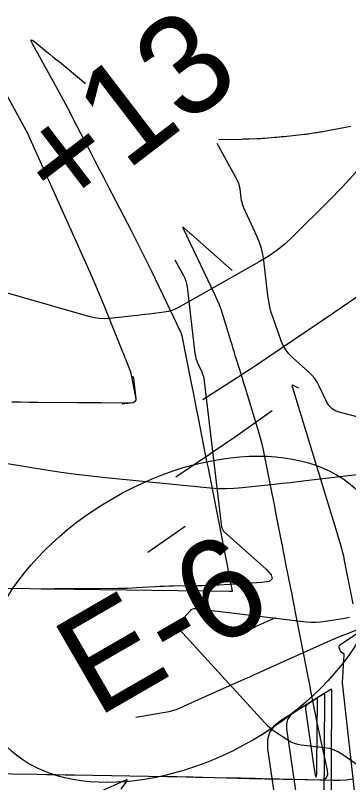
# Model space of a CAD drawing. Extents: x 1005228 to 1008882, y 1883389 to 1885754.
# Drawn here: x 1008057.01 to 1008077.87, y 1884530.66 to 1884578.71 of the extents above; entities that cross this region are included whole.
import ezdxf

# ---------------------------------------------------------------- set-up
doc = ezdxf.new("R2010")
doc.units = 0
for name, color, linetype in [('ATDIMS', 7, 'Continuous'), ('C-ANNO-NOTE', 7, 'Continuous'), ('R_Erosion', 7, 'Continuous'), ('S_BASELINE', 7, 'Continuous'), ('S_BRIDGE', 7, 'Continuous'), ('TSOBSTACLE', 7, 'Continuous')]:
    doc.layers.add(name, color=color, linetype=linetype)

msp = doc.modelspace()

# ---------------------------------------------------------------- linework, layer by layer
at = {"layer": 'ATDIMS'}
for points in [[(1008073.086, 1884553.939), (1008070.574, 1884552.176), (1008070.225, 1884551.932), (1008069.874, 1884551.689), (1008069.523, 1884551.448), (1008069.17, 1884551.209), (1008067.05, 1884549.779)], [(1008063.643, 1884530.239), (1008063.954, 1884530.685), (1008064.007, 1884530.776), (1008064.009, 1884530.824), (1008063.961, 1884530.831), (1008063.862, 1884530.795), (1008062.288, 1884530.078)]]:
    msp.add_lwpolyline(points, dxfattribs=at)
at = {"layer": 'C-ANNO-NOTE'}
for points in [[(1008078.722, 1884569.319), (1008077.714, 1884568.219), (1008077.461, 1884567.946), (1008077.204, 1884567.675), (1008076.944, 1884567.408), (1008076.681, 1884567.143), (1008074.378, 1884564.856), (1008073.893, 1884564.405), (1008073.381, 1884563.989), (1008072.842, 1884563.608), (1008072.277, 1884563.263), (1008067.228, 1884560.405), (1008067.015, 1884560.298), (1008066.796, 1884560.214), (1008066.569, 1884560.152), (1008066.334, 1884560.113), (1008065.382, 1884560.001), (1008065.144, 1884559.973), (1008064.906, 1884559.946), (1008064.668, 1884559.919), (1008064.429, 1884559.893), (1008062.915, 1884559.73), (1008062.585, 1884559.71), (1008062.257, 1884559.722), (1008061.933, 1884559.766), (1008061.61, 1884559.842), (1008046.977, 1884564.044)], [(1008077.93, 1884540.998), (1008077.629, 1884540.943), (1008076.42, 1884540.738), (1008076.118, 1884540.698), (1008075.815, 1884540.679), (1008075.512, 1884540.683), (1008075.208, 1884540.709), (1008068.293, 1884541.543), (1008068.186, 1884541.544), (1008068.089, 1884541.52), (1008068.002, 1884541.472), (1008067.924, 1884541.4), (1008067.583, 1884541.006), (1008067.535, 1884540.948), (1008067.488, 1884540.888), (1008067.444, 1884540.826), (1008067.402, 1884540.762), (1008067.24, 1884540.505), (1008067.211, 1884540.441), (1008067.205, 1884540.38), (1008067.222, 1884540.321), (1008067.262, 1884540.263), (1008072.605, 1884534.427), (1008072.764, 1884534.263), (1008072.933, 1884534.11), (1008073.111, 1884533.967), (1008073.298, 1884533.835), (1008074.064, 1884533.329), (1008074.26, 1884533.215), (1008074.465, 1884533.126), (1008074.68, 1884533.062), (1008074.903, 1884533.024), (1008076.347, 1884532.861), (1008076.657, 1884532.807), (1008076.952, 1884532.716), (1008077.234, 1884532.588), (1008077.502, 1884532.423), (1008087.661, 1884525.295)]]:
    msp.add_lwpolyline(points, dxfattribs=at)
at = {"layer": 'R_Erosion'}
msp.add_ellipse((1008067.488, 1884540.888), major_axis=(11.853, 6.865), ratio=0.638788, dxfattribs=at)
at = {"layer": 'S_BRIDGE'}
msp.add_lwpolyline([(1008055.231, 1884550.845), (1008058.949, 1884550.25), (1008059.88, 1884550.109), (1008060.812, 1884549.981), (1008061.746, 1884549.867), (1008062.682, 1884549.768), (1008069.204, 1884549.124), (1008069.704, 1884549.087), (1008070.204, 1884549.077), (1008070.704, 1884549.092), (1008071.204, 1884549.133), (1008073.203, 1884549.349), (1008073.703, 1884549.403), (1008074.202, 1884549.459), (1008074.702, 1884549.516), (1008075.201, 1884549.574), (1008079.295, 1884550.057)], dxfattribs=at)
at = {"layer": 'TSOBSTACLE'}
for points in [[(1008054.032, 1884578.139), (1008057.668, 1884571.525), (1008057.68, 1884571.501), (1008057.693, 1884571.478), (1008057.705, 1884571.454), (1008057.716, 1884571.43), (1008057.763, 1884571.334), (1008057.774, 1884571.31), (1008057.786, 1884571.286), (1008057.797, 1884571.262), (1008057.808, 1884571.238), (1008057.897, 1884571.038), (1008061.585, 1884562.819), (1008061.823, 1884562.281), (1008062.056, 1884561.741), (1008062.283, 1884561.199), (1008062.505, 1884560.654), (1008063.721, 1884557.631), (1008063.771, 1884557.506), (1008063.821, 1884557.381), (1008063.871, 1884557.256), (1008063.922, 1884557.131), (1008064.184, 1884556.479), (1008064.203, 1884556.43), (1008064.219, 1884556.38), (1008064.233, 1884556.329), (1008064.244, 1884556.278), (1008064.285, 1884556.07), (1008064.306, 1884555.966), (1008064.326, 1884555.863), (1008064.535, 1884554.8), (1008064.544, 1884554.63), (1008064.493, 1884554.509), (1008064.384, 1884554.437), (1008064.215, 1884554.415), (1008062.385, 1884554.433), (1008062.014, 1884554.436), (1008061.643, 1884554.44), (1008061.272, 1884554.443), (1008060.901, 1884554.447), (1008058.408, 1884554.468), (1008057.869, 1884554.472), (1008057.33, 1884554.476), (1008056.791, 1884554.478)], [(1008054.5, 1884542.843), (1008057.932, 1884542.81), (1008058.626, 1884542.803), (1008059.319, 1884542.795), (1008060.013, 1884542.786), (1008060.706, 1884542.777), (1008070.384, 1884542.64), (1008070.427, 1884542.64), (1008070.47, 1884542.639), (1008070.576, 1884542.637), (1008070.586, 1884542.638), (1008070.592, 1884542.642), (1008070.595, 1884542.649), (1008070.595, 1884542.659), (1008070.58, 1884542.732), (1008070.576, 1884542.756), (1008069.26, 1884549.485), (1008069.176, 1884549.916), (1008069.091, 1884550.346), (1008069.006, 1884550.776), (1008068.921, 1884551.206), (1008068.488, 1884553.387), (1008068.448, 1884553.587), (1008068.409, 1884553.787), (1008068.369, 1884553.987), (1008068.33, 1884554.187), (1008068.173, 1884554.987), (1008068.133, 1884555.187), (1008068.094, 1884555.387), (1008068.054, 1884555.587), (1008068.015, 1884555.787), (1008067.45, 1884558.638), (1008067.448, 1884558.648), (1008067.445, 1884558.659), (1008067.443, 1884558.669), (1008067.44, 1884558.679), (1008067.418, 1884558.749), (1008067.412, 1884558.768), (1008067.409, 1884558.777), (1008067.405, 1884558.786), (1008067.366, 1884558.868), (1008065.55, 1884562.657), (1008065.244, 1884563.29), (1008064.932, 1884563.92), (1008064.616, 1884564.549), (1008064.294, 1884565.174), (1008062.803, 1884568.049), (1008062.539, 1884568.556), (1008062.276, 1884569.063), (1008062.013, 1884569.57), (1008061.75, 1884570.078), (1008060.698, 1884572.107), (1008060.434, 1884572.613), (1008060.166, 1884573.118), (1008059.895, 1884573.621), (1008059.621, 1884574.123), (1008058.08, 1884576.926), (1008058.001, 1884577.094), (1008057.998, 1884577.17), (1008058.072, 1884577.154), (1008058.224, 1884577.046), (1008058.983, 1884576.426), (1008059.173, 1884576.272), (1008059.363, 1884576.117), (1008059.553, 1884575.962), (1008059.743, 1884575.807), (1008061.406, 1884574.447)], [(1008078.007, 1884571.751), (1008076.126, 1884571.399), (1008076.041, 1884571.384), (1008075.957, 1884571.369), (1008075.872, 1884571.355), (1008075.788, 1884571.341), (1008075.449, 1884571.289), (1008075.364, 1884571.276), (1008075.279, 1884571.265), (1008075.194, 1884571.254), (1008075.109, 1884571.244), (1008073.826, 1884571.106), (1008073.68, 1884571.09), (1008073.534, 1884571.076), (1008073.388, 1884571.063), (1008073.241, 1884571.05), (1008072.601, 1884570.998), (1008072.482, 1884570.989), (1008072.363, 1884570.981), (1008072.244, 1884570.975), (1008072.125, 1884570.97), (1008071.648, 1884570.953), (1008071.529, 1884570.949), (1008071.41, 1884570.945), (1008071.29, 1884570.943), (1008071.171, 1884570.941), (1008069.742, 1884570.919)], [(1008078.727, 1884553.491), (1008077.274, 1884553.858), (1008077.025, 1884553.949), (1008076.813, 1884554.085), (1008076.639, 1884554.266), (1008076.502, 1884554.493), (1008076.031, 1884555.493), (1008075.902, 1884555.734), (1008075.751, 1884555.96), (1008075.578, 1884556.168), (1008075.383, 1884556.36), (1008074.35, 1884557.282), (1008074.126, 1884557.508), (1008073.935, 1884557.756), (1008073.777, 1884558.027), (1008073.652, 1884558.32), (1008073.143, 1884559.758), (1008073.031, 1884560.101), (1008072.94, 1884560.449), (1008072.868, 1884560.801), (1008072.816, 1884561.158), (1008072.56, 1884563.347), (1008072.5, 1884563.731), (1008072.411, 1884564.107), (1008072.293, 1884564.476), (1008072.146, 1884564.836), (1008071.3, 1884566.705), (1008071.244, 1884566.841), (1008071.2, 1884566.979), (1008071.166, 1884567.121), (1008071.144, 1884567.265), (1008071.075, 1884567.85), (1008071.051, 1884567.994), (1008071.013, 1884568.134), (1008070.963, 1884568.269), (1008070.899, 1884568.4), (1008069.653, 1884570.675)], [(1008055.129, 1884531.232), (1008058.394, 1884531.177), (1008058.969, 1884531.167), (1008059.544, 1884531.158), (1008060.119, 1884531.148), (1008060.695, 1884531.139), (1008066.52, 1884531.043), (1008066.668, 1884531.04), (1008066.815, 1884531.038), (1008066.963, 1884531.035), (1008067.111, 1884531.032), (1008067.702, 1884531.021), (1008067.849, 1884531.018), (1008067.997, 1884531.015), (1008068.145, 1884531.012), (1008068.293, 1884531.009), (1008070.674, 1884530.959), (1008071.12, 1884530.949), (1008071.567, 1884530.939), (1008072.013, 1884530.928), (1008072.459, 1884530.917), (1008076.043, 1884530.823), (1008076.319, 1884530.856), (1008076.496, 1884530.97), (1008076.575, 1884531.166), (1008076.554, 1884531.443), (1008076.178, 1884533.157), (1008076.156, 1884533.254), (1008076.135, 1884533.352), (1008076.113, 1884533.449), (1008076.092, 1884533.546), (1008076.005, 1884533.935), (1008075.983, 1884534.032), (1008075.963, 1884534.13), (1008075.943, 1884534.228), (1008075.923, 1884534.325), (1008075.494, 1884536.509), (1008075.48, 1884536.584), (1008075.465, 1884536.658), (1008075.45, 1884536.733), (1008075.436, 1884536.808), (1008075.376, 1884537.106), (1008075.362, 1884537.181), (1008075.347, 1884537.256), (1008075.332, 1884537.33), (1008075.318, 1884537.405), (1008074.555, 1884541.303), (1008074.48, 1884541.685), (1008074.404, 1884542.067), (1008074.329, 1884542.449), (1008074.253, 1884542.831), (1008073.95, 1884544.358), (1008073.874, 1884544.74), (1008073.799, 1884545.122), (1008073.724, 1884545.504), (1008073.649, 1884545.886), (1008073.323, 1884547.556), (1008073.243, 1884547.962), (1008073.163, 1884548.368), (1008073.083, 1884548.773), (1008073.003, 1884549.179), (1008072.631, 1884551.051), (1008072.537, 1884551.497), (1008072.431, 1884551.94), (1008072.315, 1884552.38), (1008072.187, 1884552.817), (1008071.39, 1884555.423), (1008071.316, 1884555.664), (1008071.242, 1884555.905), (1008071.169, 1884556.146), (1008071.095, 1884556.387), (1008070.8, 1884557.351), (1008070.726, 1884557.592), (1008070.652, 1884557.832), (1008070.578, 1884558.073), (1008070.504, 1884558.314), (1008070.019, 1884559.894), (1008069.907, 1884560.235), (1008069.782, 1884560.571), (1008069.646, 1884560.902), (1008069.496, 1884561.229), (1008067.508, 1884565.373), (1008067.487, 1884565.425), (1008067.488, 1884565.448), (1008067.51, 1884565.443), (1008067.554, 1884565.408), (1008067.94, 1884565.067), (1008067.995, 1884565.018), (1008070.582, 1884562.728)], [(1008066.994, 1884563.399), (1008067.537, 1884562.407), (1008067.619, 1884562.239), (1008067.684, 1884562.065), (1008067.732, 1884561.886), (1008067.763, 1884561.701), (1008068.255, 1884557.527), (1008068.279, 1884557.375), (1008068.314, 1884557.227), (1008068.361, 1884557.082), (1008068.419, 1884556.94), (1008068.673, 1884556.378), (1008068.731, 1884556.236), (1008068.778, 1884556.091), (1008068.813, 1884555.942), (1008068.837, 1884555.79), (1008069.884, 1884546.848), (1008069.89, 1884546.804), (1008069.899, 1884546.761), (1008069.91, 1884546.718), (1008069.924, 1884546.676), (1008069.983, 1884546.509), (1008070, 1884546.469), (1008070.022, 1884546.431), (1008070.048, 1884546.397), (1008070.079, 1884546.366), (1008072.732, 1884543.999), (1008073.031, 1884543.666), (1008073.083, 1884543.419), (1008072.888, 1884543.257), (1008072.448, 1884543.182), (1008069.747, 1884543.025), (1008069.406, 1884543.007), (1008069.064, 1884542.994), (1008068.723, 1884542.984), (1008068.381, 1884542.978), (1008066.907, 1884542.962), (1008066.618, 1884542.957), (1008066.33, 1884542.948), (1008066.042, 1884542.936), (1008065.754, 1884542.92), (1008064.603, 1884542.848), (1008064.315, 1884542.832), (1008064.026, 1884542.821), (1008063.738, 1884542.814), (1008063.45, 1884542.811), (1008059.548, 1884542.803), (1008059.54, 1884542.803), (1008059.531, 1884542.802), (1008059.523, 1884542.802), (1008059.515, 1884542.801), (1008059.465, 1884542.794)], [(1008078.526, 1884561.173), (1008077.535, 1884560.477), (1008077.37, 1884560.362), (1008077.204, 1884560.247), (1008077.037, 1884560.133), (1008076.87, 1884560.02), (1008072.048, 1884556.767), (1008071.721, 1884556.548), (1008071.392, 1884556.331), (1008071.063, 1884556.116), (1008070.732, 1884555.904), (1008068.741, 1884554.632)], [(1008064.335, 1884556.123), (1008064.382, 1884556.038), (1008064.389, 1884556.023), (1008064.394, 1884556.009), (1008064.398, 1884555.993), (1008064.401, 1884555.978), (1008064.552, 1884554.698), (1008064.549, 1884554.599), (1008064.516, 1884554.525), (1008064.452, 1884554.474), (1008064.356, 1884554.448), (1008063.692, 1884554.362)], [(1008074.758, 1884555.352), (1008074.408, 1884555.537), (1008074.359, 1884555.556), (1008074.33, 1884555.551), (1008074.32, 1884555.523), (1008074.33, 1884555.472), (1008076.647, 1884547.896), (1008076.731, 1884547.62), (1008076.815, 1884547.344), (1008076.9, 1884547.068), (1008076.984, 1884546.792), (1008077.32, 1884545.688), (1008077.401, 1884545.411), (1008077.474, 1884545.133), (1008077.541, 1884544.852), (1008077.601, 1884544.57), (1008078.139, 1884541.857)], [(1008067.646, 1884546.706), (1008065.311, 1884545.066)], [(1008071.195, 1884540.048), (1008071.843, 1884540.338), (1008071.941, 1884540.382), (1008072.039, 1884540.425), (1008072.136, 1884540.469), (1008072.234, 1884540.514), (1008073.31, 1884540.999)], [(1008064.541, 1884534.761), (1008066.517, 1884535.099), (1008066.726, 1884535.142), (1008066.931, 1884535.197), (1008067.132, 1884535.265), (1008067.329, 1884535.346), (1008068.89, 1884536.043), (1008071.383, 1884537.158), (1008071.682, 1884537.292), (1008071.982, 1884537.426), (1008072.281, 1884537.561), (1008072.58, 1884537.696), (1008076.479, 1884539.455), (1008076.753, 1884539.576), (1008077.029, 1884539.693), (1008077.307, 1884539.807), (1008077.586, 1884539.916), (1008078.706, 1884540.346)], [(1008078.767, 1884540.228), (1008077.298, 1884539.246), (1008077.269, 1884539.22), (1008077.252, 1884539.19), (1008077.249, 1884539.156), (1008077.258, 1884539.118), (1008077.359, 1884538.866), (1008077.362, 1884538.862), (1008077.365, 1884538.859), (1008077.524, 1884538.755), (1008077.548, 1884538.736), (1008077.564, 1884538.713), (1008077.573, 1884538.686), (1008077.575, 1884538.655), (1008077.465, 1884536.927), (1008077.465, 1884536.919), (1008077.465, 1884536.917), (1008078.333, 1884529.235)], [(1008076.77, 1884526.651), (1008076.83, 1884536.435), (1008076.825, 1884536.471), (1008076.811, 1884536.491), (1008076.787, 1884536.494), (1008076.753, 1884536.48), (1008076.597, 1884536.394), (1008076.558, 1884536.372), (1008076.52, 1884536.35), (1008076.482, 1884536.327), (1008076.444, 1884536.304), (1008073.602, 1884534.535), (1008073.186, 1884534.2), (1008072.913, 1884533.798), (1008072.783, 1884533.33), (1008072.794, 1884532.797), (1008074.429, 1884521.599)], [(1008067.99, 1884531.012), (1008071.662, 1884530.921), (1008071.898, 1884530.915), (1008072.134, 1884530.91), (1008072.371, 1884530.906), (1008072.607, 1884530.902), (1008073.552, 1884530.887), (1008073.788, 1884530.883), (1008074.025, 1884530.878), (1008074.261, 1884530.873), (1008074.497, 1884530.867), (1008076.873, 1884530.802), (1008077.3, 1884530.805), (1008077.724, 1884530.835), (1008078.145, 1884530.894)]]:
    msp.add_lwpolyline(points, dxfattribs=at)
for points in [[(1008074.051, 1884534.62), (1008073.973, 1884534.343), (1008073.98, 1884534.027), (1008075.668, 1884522.463), (1008075.93, 1884520.936), (1008076.121, 1884520.434), (1008076.24, 1884520.958), (1008076.289, 1884522.506), (1008076.373, 1884536.184), (1008076.37, 1884536.205), (1008076.361, 1884536.217), (1008076.347, 1884536.219), (1008076.327, 1884536.211), (1008076.235, 1884536.16), (1008076.212, 1884536.147), (1008076.189, 1884536.133), (1008076.166, 1884536.12), (1008076.144, 1884536.106), (1008074.459, 1884535.058), (1008074.212, 1884534.859)], [(1008075.188, 1884535.443), (1008075.164, 1884535.356), (1008075.166, 1884535.257), (1008075.695, 1884531.633), (1008075.777, 1884531.154), (1008075.837, 1884530.997), (1008075.874, 1884531.161), (1008075.889, 1884531.646), (1008075.916, 1884535.933), (1008075.915, 1884535.939), (1008075.912, 1884535.943), (1008075.908, 1884535.944), (1008075.901, 1884535.941), (1008075.872, 1884535.925), (1008075.858, 1884535.917), (1008075.844, 1884535.908), (1008075.316, 1884535.58), (1008075.239, 1884535.517)]]:
    msp.add_lwpolyline(points, close=True, dxfattribs=at)

# ---------------------------------------------------------------- texts
at = {"layer": 'R_Erosion'}
msp.add_text('E-6', height=6.2498, rotation=30.0784, dxfattribs=at).set_placement((1008062.111, 1884534.695))
at = {"layer": 'S_BASELINE'}
msp.add_text('+13', height=6.2498, rotation=37.4532, dxfattribs=at).set_placement((1008060.072, 1884565.955))

doc.saveas('drawing.dxf')
